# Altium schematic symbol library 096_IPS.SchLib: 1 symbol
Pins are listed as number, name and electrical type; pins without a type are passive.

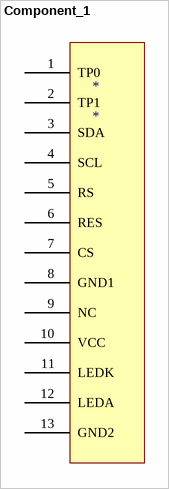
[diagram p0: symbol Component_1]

## Component_1
designator *
pins: 1 TP0, 2 TP1, 3 SDA, 4 SCL, 5 RS, 6 RES, 7 CS, 8 GND1, 9 NC, 10 VCC, 11 LEDK, 12 LEDA, 13 GND2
